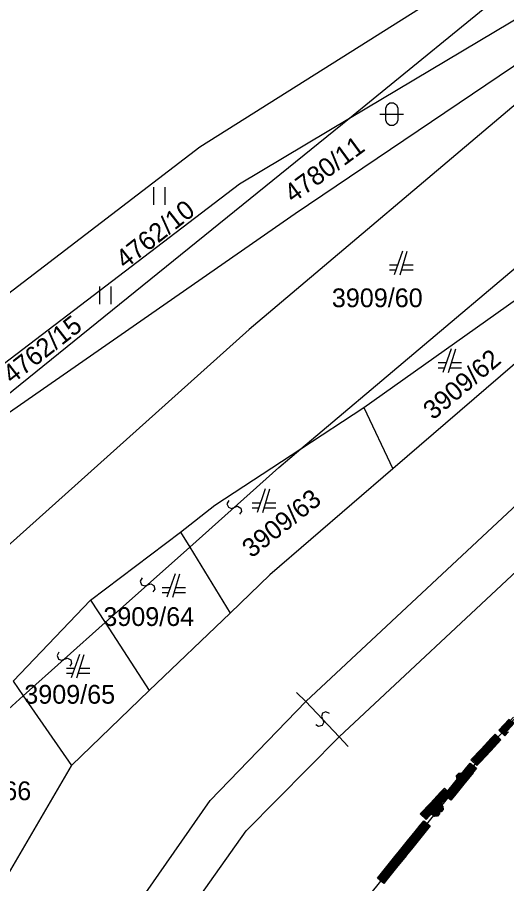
# Model space of a CAD drawing. Extents: x -266179 to -264727, y -1243225 to -1241702.
# Drawn here: x -265607.4 to -265565.7, y -1243155 to -1243081.2 of the extents above; entities that cross this region are included whole.
import ezdxf

# ---------------------------------------------------------------- set-up
doc = ezdxf.new("R2010")
doc.units = 0
for name, color, linetype in [('Vrstva 1', 7, 'Continuous'), ('Vrstva 19', 7, 'Continuous'), ('Vrstva 2', 7, 'Continuous'), ('Vrstva 21', 7, 'Continuous')]:
    doc.layers.add(name, color=color, linetype=linetype)

msp = doc.modelspace()

# ---------------------------------------------------------------- linework, layer by layer
at = {"layer": 'Vrstva 1'}
for p, q in [((-265545.67, -1243063.18), (-265591.88, -1243092.3)), ((-265579.13, -1243089.82), (-265534.79, -1243063.37)), ((-265577.11, -1243088.19), (-265556.47, -1243071.33)), ((-265563.36, -1243084.21), (-265583.76, -1243097.98)), ((-265560.69, -1243085), (-265587.67, -1243107.82)), ((-265579.13, -1243089.82), (-265577.11, -1243088.19)), ((-265622.55, -1243124.94), (-265579.13, -1243089.82)), ((-265588.51, -1243095.42), (-265579.13, -1243089.82)), ((-265591.88, -1243092.3), (-265615.8, -1243110.62)), ((-265619.14, -1243118.79), (-265588.51, -1243095.42)), ((-265595.83, -1243095.71), (-265595.83, -1243097.21)), ((-265594.83, -1243097.21), (-265594.83, -1243095.71)), ((-265583.76, -1243097.98), (-265622.55, -1243124.94)), ((-265577.91, -1243114.48), (-265559.8, -1243101.6)), ((-265574.62, -1243101.16), (-265575.32, -1243103.16)), ((-265574.82, -1243103.16), (-265574.22, -1243101.16)), ((-265575.04, -1243102.36), (-265575.72, -1243102.36)), ((-265573.72, -1243102.36), (-265574.58, -1243102.36)), ((-265575.72, -1243102.76), (-265575.18, -1243102.76)), ((-265574.7, -1243102.76), (-265573.72, -1243102.76)), ((-265600.43, -1243104.18), (-265600.43, -1243105.68)), ((-265599.43, -1243105.68), (-265599.43, -1243104.18)), ((-265558.41, -1243105), (-265575.44, -1243119.69)), ((-265587.67, -1243107.82), (-265623.99, -1243140.37)), ((-265570.49, -1243109.48), (-265571.19, -1243111.48)), ((-265570.69, -1243111.48), (-265570.09, -1243109.48)), ((-265570.91, -1243110.68), (-265571.59, -1243110.68)), ((-265569.59, -1243110.68), (-265570.45, -1243110.68)), ((-265571.59, -1243111.08), (-265571.05, -1243111.08)), ((-265570.57, -1243111.08), (-265569.59, -1243111.08)), ((-265583.27, -1243117.99), (-265577.91, -1243114.48)), ((-265577.91, -1243114.48), (-265575.44, -1243119.69)), ((-265590.59, -1243122.79), (-265583.27, -1243117.99)), ((-265575.44, -1243119.69), (-265585.91, -1243128.72)), ((-265586.31, -1243121.41), (-265587.01, -1243123.41)), ((-265586.51, -1243123.41), (-265585.91, -1243121.41)), ((-265593.52, -1243125.08), (-265590.59, -1243122.79)), ((-265586.73, -1243122.61), (-265587.41, -1243122.61)), ((-265587.41, -1243123.01), (-265586.87, -1243123.01)), ((-265586.39, -1243123.01), (-265585.41, -1243123.01)), ((-265585.41, -1243122.61), (-265586.27, -1243122.61)), ((-265601.18, -1243130.87), (-265593.52, -1243125.08)), ((-265593.52, -1243125.08), (-265592.74, -1243126.36)), ((-265592.74, -1243126.36), (-265589.31, -1243131.99)), ((-265593.99, -1243128.63), (-265594.69, -1243130.63)), ((-265594.19, -1243130.63), (-265593.59, -1243128.63)), ((-265585.91, -1243128.72), (-265589.31, -1243131.99)), ((-265594.41, -1243129.83), (-265595.09, -1243129.83)), ((-265593.09, -1243129.83), (-265593.95, -1243129.83)), ((-265595.09, -1243130.23), (-265594.55, -1243130.23)), ((-265594.07, -1243130.23), (-265593.09, -1243130.23)), ((-265607.78, -1243137.78), (-265601.18, -1243130.87)), ((-265601.18, -1243130.87), (-265599.93, -1243132.79)), ((-265589.31, -1243131.99), (-265596.18, -1243138.59)), ((-265599.93, -1243132.79), (-265596.18, -1243138.59)), ((-265602.14, -1243135.5), (-265602.84, -1243137.5)), ((-265602.34, -1243137.5), (-265601.74, -1243135.5)), ((-265602.56, -1243136.7), (-265603.24, -1243136.7)), ((-265603.24, -1243137.1), (-265602.7, -1243137.1)), ((-265602.22, -1243137.1), (-265601.24, -1243137.1)), ((-265601.24, -1243136.7), (-265602.1, -1243136.7)), ((-265607.78, -1243137.78), (-265606.91, -1243139.03)), ((-265596.18, -1243138.59), (-265602.8, -1243144.96)), ((-265606.91, -1243139.03), (-265602.8, -1243144.96)), ((-265565.22, -1243141.2), (-265567.42, -1243143.54)), ((-265567.42, -1243143.54), (-265575.88, -1243154.04)), ((-265602.84, -1243145), (-265608.61, -1243154.88)), ((-265602.8, -1243144.96), (-265602.84, -1243145)), ((-265575.88, -1243154.04), (-265581.59, -1243161.13))]:
    msp.add_line(p, q, dxfattribs=at)
msp.add_lwpolyline([(-265576.04, -1243088.99), (-265575.94, -1243088.7), (-265575.69, -1243088.52), (-265575.38, -1243088.52), (-265575.13, -1243088.7), (-265575.03, -1243088.99), (-265575.03, -1243089.99), (-265575.13, -1243090.28), (-265575.38, -1243090.46), (-265575.69, -1243090.46), (-265575.94, -1243090.28), (-265576.04, -1243089.99)], close=True, dxfattribs=at)
msp.add_lwpolyline([(-265576.54, -1243089.49), (-265575.27, -1243089.49), (-265574.54, -1243089.49)], dxfattribs=at)
at = {"layer": 'Vrstva 19'}
for p, q in [((-265565.22, -1243141.2), (-265567.42, -1243143.54)), ((-265567.42, -1243143.54), (-265575.88, -1243154.04)), ((-265575.88, -1243154.04), (-265581.59, -1243161.13))]:
    msp.add_line(p, q, dxfattribs=at)
for points in [[(-265565.161, -1243140.846), (-265566.031, -1243141.772), (-265566.264, -1243142.019), (-265566.322, -1243141.965), (-265565.452, -1243141.039)], [(-265565.044, -1243140.956), (-265565.914, -1243141.881), (-265566.147, -1243142.129), (-265566.205, -1243142.074), (-265565.336, -1243141.149)], [(-265565.582, -1243142.097), (-265565.897, -1243142.432), (-265566.407, -1243141.953), (-265565.537, -1243141.028)], [(-265564.928, -1243141.065), (-265565.798, -1243141.991), (-265566.03, -1243142.238), (-265566.089, -1243142.184), (-265565.219, -1243141.258)], [(-265565.681, -1243142.1), (-265565.914, -1243142.348), (-265565.972, -1243142.293), (-265565.102, -1243141.368)], [(-265566.233, -1243142.787), (-265567.103, -1243143.712), (-265567.972, -1243144.638), (-265568.287, -1243144.973), (-265568.797, -1243144.494), (-265567.928, -1243143.568), (-265567.058, -1243142.643), (-265566.743, -1243142.308), (-265566.233, -1243142.787), (-265566.318, -1243142.775), (-265567.188, -1243143.701), (-265568.058, -1243144.626), (-265568.29, -1243144.874), (-265568.349, -1243144.819), (-265567.479, -1243143.894), (-265566.609, -1243142.968), (-265566.376, -1243142.721), (-265566.435, -1243142.666), (-265567.304, -1243143.591), (-265568.174, -1243144.517), (-265568.407, -1243144.765), (-265568.465, -1243144.71), (-265567.596, -1243143.784), (-265566.726, -1243142.859), (-265566.493, -1243142.611), (-265566.551, -1243142.556), (-265567.421, -1243143.482), (-265568.291, -1243144.407), (-265568.524, -1243144.655), (-265568.582, -1243144.6), (-265567.712, -1243143.675), (-265566.842, -1243142.749), (-265566.61, -1243142.502), (-265566.668, -1243142.447), (-265567.538, -1243143.372), (-265568.407, -1243144.298), (-265568.64, -1243144.545), (-265568.698, -1243144.491), (-265567.829, -1243143.565), (-265566.959, -1243142.64), (-265566.726, -1243142.392)], [(-265568.611, -1243145.578), (-265569.408, -1243146.567), (-265570.205, -1243147.555), (-265570.494, -1243147.913), (-265571.039, -1243147.474), (-265570.242, -1243146.485), (-265569.445, -1243145.497), (-265569.156, -1243145.138), (-265568.611, -1243145.578), (-265568.697, -1243145.573), (-265569.494, -1243146.562), (-265570.291, -1243147.55), (-265570.504, -1243147.815), (-265570.567, -1243147.765), (-265569.77, -1243146.776), (-265568.973, -1243145.787), (-265568.759, -1243145.523), (-265568.822, -1243145.472), (-265569.619, -1243146.461), (-265570.416, -1243147.45), (-265570.629, -1243147.715), (-265570.691, -1243147.664), (-265569.894, -1243146.676), (-265569.097, -1243145.687), (-265568.884, -1243145.422), (-265568.946, -1243145.372), (-265569.743, -1243146.361), (-265570.54, -1243147.35), (-265570.754, -1243147.614), (-265570.816, -1243147.564), (-265570.019, -1243146.575), (-265569.222, -1243145.586), (-265569.009, -1243145.322), (-265569.071, -1243145.271), (-265569.868, -1243146.26), (-265570.665, -1243147.249), (-265570.878, -1243147.514), (-265570.941, -1243147.464), (-265570.144, -1243146.475), (-265569.347, -1243145.486), (-265569.133, -1243145.221)], [(-265568.308, -1243145.201), (-265569.105, -1243146.19), (-265569.902, -1243147.178), (-265570.19, -1243147.536), (-265570.735, -1243147.097), (-265569.938, -1243146.108), (-265569.141, -1243145.12), (-265568.853, -1243144.761), (-265568.308, -1243145.201), (-265568.393, -1243145.196), (-265569.19, -1243146.185), (-265569.987, -1243147.173), (-265570.201, -1243147.438), (-265570.263, -1243147.388), (-265569.466, -1243146.399), (-265568.669, -1243145.41), (-265568.456, -1243145.146), (-265568.518, -1243145.095), (-265569.315, -1243146.084), (-265570.112, -1243147.073), (-265570.325, -1243147.338), (-265570.388, -1243147.287), (-265569.591, -1243146.299), (-265568.794, -1243145.31), (-265568.58, -1243145.045), (-265568.643, -1243144.995), (-265569.44, -1243145.984), (-265570.237, -1243146.973), (-265570.45, -1243147.237), (-265570.512, -1243147.187), (-265569.715, -1243146.198), (-265568.918, -1243145.209), (-265568.705, -1243144.945), (-265568.767, -1243144.895), (-265569.564, -1243145.883), (-265570.361, -1243146.872), (-265570.574, -1243147.137), (-265570.637, -1243147.087), (-265569.84, -1243146.098), (-265569.043, -1243145.109), (-265568.829, -1243144.844)], [(-265569.35, -1243146.06), (-265569.535, -1243146.257), (-265569.804, -1243146.265), (-265570, -1243146.08), (-265570.009, -1243145.812), (-265569.824, -1243145.615), (-265569.555, -1243145.607), (-265569.358, -1243145.792), (-265569.35, -1243146.06), (-265569.386, -1243146.04), (-265569.55, -1243146.215), (-265569.664, -1243146.218), (-265569.39, -1243145.927), (-265569.393, -1243145.814), (-265569.777, -1243146.222), (-265569.835, -1243146.167), (-265569.451, -1243145.759), (-265569.51, -1243145.704), (-265569.893, -1243146.112), (-265569.952, -1243146.058), (-265569.568, -1243145.649), (-265569.681, -1243145.653), (-265569.955, -1243145.944), (-265569.959, -1243145.831), (-265569.794, -1243145.656)], [(-265570.547, -1243147.378), (-265571.417, -1243148.303), (-265572.287, -1243149.229), (-265572.602, -1243149.564), (-265573.112, -1243149.084), (-265572.242, -1243148.159), (-265571.372, -1243147.234), (-265571.057, -1243146.898), (-265570.547, -1243147.378), (-265570.646, -1243147.381), (-265571.516, -1243148.306), (-265572.386, -1243149.232), (-265572.619, -1243149.479), (-265572.677, -1243149.425), (-265571.807, -1243148.499), (-265570.937, -1243147.574), (-265570.705, -1243147.326), (-265570.763, -1243147.271), (-265571.633, -1243148.197), (-265572.502, -1243149.122), (-265572.735, -1243149.37), (-265572.793, -1243149.315), (-265571.924, -1243148.39), (-265571.054, -1243147.464), (-265570.821, -1243147.216), (-265570.879, -1243147.162), (-265571.749, -1243148.087), (-265572.619, -1243149.013), (-265572.852, -1243149.26), (-265572.91, -1243149.205), (-265572.04, -1243148.28), (-265571.171, -1243147.355), (-265570.938, -1243147.107), (-265570.996, -1243147.052), (-265571.866, -1243147.977), (-265572.736, -1243148.903), (-265572.968, -1243149.151), (-265573.027, -1243149.096), (-265572.157, -1243148.17), (-265571.287, -1243147.245), (-265571.054, -1243146.997)], [(-265571.167, -1243148.701), (-265571.337, -1243148.911), (-265571.604, -1243148.94), (-265571.814, -1243148.771), (-265571.843, -1243148.503), (-265571.673, -1243148.293), (-265571.406, -1243148.265), (-265571.196, -1243148.434), (-265571.167, -1243148.701), (-265571.205, -1243148.684), (-265571.355, -1243148.871), (-265571.468, -1243148.883), (-265571.217, -1243148.571), (-265571.229, -1243148.459), (-265571.58, -1243148.895), (-265571.643, -1243148.845), (-265571.291, -1243148.409), (-265571.354, -1243148.358), (-265571.705, -1243148.794), (-265571.767, -1243148.744), (-265571.416, -1243148.308), (-265571.528, -1243148.32), (-265571.779, -1243148.632), (-265571.791, -1243148.519), (-265571.641, -1243148.332)], [(-265571.471, -1243149.078), (-265571.641, -1243149.288), (-265571.908, -1243149.317), (-265572.118, -1243149.148), (-265572.147, -1243148.88), (-265571.977, -1243148.67), (-265571.71, -1243148.641), (-265571.5, -1243148.811), (-265571.471, -1243149.078), (-265571.509, -1243149.061), (-265571.659, -1243149.248), (-265571.772, -1243149.26), (-265571.521, -1243148.948), (-265571.533, -1243148.836), (-265571.884, -1243149.272), (-265571.946, -1243149.222), (-265571.595, -1243148.786), (-265571.657, -1243148.735), (-265572.009, -1243149.171), (-265572.071, -1243149.121), (-265571.72, -1243148.685), (-265571.832, -1243148.697), (-265572.083, -1243149.009), (-265572.095, -1243148.896), (-265571.945, -1243148.709)], [(-265572.261, -1243150.106), (-265573.058, -1243151.095), (-265573.855, -1243152.083), (-265574.144, -1243152.442), (-265574.689, -1243152.002), (-265573.892, -1243151.013), (-265573.095, -1243150.025), (-265572.806, -1243149.667), (-265572.261, -1243150.106), (-265572.359, -1243150.116), (-265573.156, -1243151.105), (-265573.953, -1243152.094), (-265574.167, -1243152.359), (-265574.229, -1243152.309), (-265573.432, -1243151.32), (-265572.635, -1243150.331), (-265572.422, -1243150.066), (-265572.484, -1243150.016), (-265573.281, -1243151.005), (-265574.078, -1243151.994), (-265574.291, -1243152.258), (-265574.354, -1243152.208), (-265573.557, -1243151.219), (-265572.76, -1243150.23), (-265572.546, -1243149.966), (-265572.609, -1243149.916), (-265573.406, -1243150.904), (-265574.203, -1243151.893), (-265574.416, -1243152.158), (-265574.478, -1243152.108), (-265573.681, -1243151.119), (-265572.884, -1243150.13), (-265572.671, -1243149.865), (-265572.733, -1243149.815), (-265573.53, -1243150.804), (-265574.327, -1243151.793), (-265574.541, -1243152.057), (-265574.603, -1243152.007), (-265573.806, -1243151.018), (-265573.009, -1243150.03), (-265572.796, -1243149.765)], [(-265572.565, -1243150.483), (-265573.362, -1243151.472), (-265574.159, -1243152.46), (-265574.447, -1243152.819), (-265574.992, -1243152.379), (-265574.195, -1243151.39), (-265573.398, -1243150.402), (-265573.11, -1243150.044), (-265572.565, -1243150.483), (-265572.663, -1243150.493), (-265573.46, -1243151.482), (-265574.257, -1243152.471), (-265574.471, -1243152.736), (-265574.533, -1243152.685), (-265573.736, -1243151.697), (-265572.939, -1243150.708), (-265572.726, -1243150.443), (-265572.788, -1243150.393), (-265573.585, -1243151.382), (-265574.382, -1243152.371), (-265574.595, -1243152.635), (-265574.657, -1243152.585), (-265573.86, -1243151.596), (-265573.063, -1243150.607), (-265572.85, -1243150.343), (-265572.912, -1243150.293), (-265573.709, -1243151.281), (-265574.506, -1243152.27), (-265574.72, -1243152.535), (-265574.782, -1243152.485), (-265573.985, -1243151.496), (-265573.188, -1243150.507), (-265572.975, -1243150.242), (-265573.037, -1243150.192), (-265573.834, -1243151.181), (-265574.631, -1243152.17), (-265574.844, -1243152.434), (-265574.907, -1243152.384), (-265574.11, -1243151.395), (-265573.313, -1243150.407), (-265573.099, -1243150.142)], [(-265574.322, -1243152.667), (-265575.119, -1243153.656), (-265575.916, -1243154.644), (-265576.205, -1243155.003), (-265576.75, -1243154.563), (-265575.953, -1243153.575), (-265575.156, -1243152.586), (-265574.867, -1243152.228), (-265574.322, -1243152.667), (-265574.408, -1243152.662), (-265575.205, -1243153.651), (-265576.002, -1243154.639), (-265576.216, -1243154.904), (-265576.278, -1243154.854), (-265575.481, -1243153.865), (-265574.684, -1243152.876), (-265574.471, -1243152.612), (-265574.533, -1243152.561), (-265575.33, -1243153.55), (-265576.127, -1243154.539), (-265576.34, -1243154.804), (-265576.402, -1243154.754), (-265575.605, -1243153.765), (-265574.808, -1243152.776), (-265574.595, -1243152.511), (-265574.657, -1243152.461), (-265575.454, -1243153.45), (-265576.251, -1243154.439), (-265576.465, -1243154.703), (-265576.527, -1243154.653), (-265575.73, -1243153.664), (-265574.933, -1243152.676), (-265574.72, -1243152.411), (-265574.782, -1243152.361), (-265575.579, -1243153.349), (-265576.376, -1243154.338), (-265576.589, -1243154.603), (-265576.652, -1243154.553), (-265575.855, -1243153.564), (-265575.058, -1243152.575), (-265574.844, -1243152.31)]]:
    msp.add_lwpolyline(points, dxfattribs=at)
at = {"layer": 'Vrstva 2'}
for p, q in [((-265583.27, -1243117.99), (-265558.79, -1243097.3)), ((-265585.16, -1243119.59), (-265583.27, -1243117.99)), ((-265592.74, -1243126.36), (-265585.16, -1243119.59)), ((-265582.84, -1243139.51), (-265564.83, -1243122.67)), ((-265580.02, -1243142.51), (-265561.87, -1243125.56)), ((-265599.93, -1243132.79), (-265592.74, -1243126.36)), ((-265606.91, -1243139.03), (-265599.93, -1243132.79)), ((-265583.64, -1243138.75), (-265582.84, -1243139.51)), ((-265615.04, -1243146.29), (-265606.91, -1243139.03)), ((-265591, -1243147.94), (-265582.84, -1243139.51)), ((-265582.84, -1243139.51), (-265580.02, -1243142.51)), ((-265587.92, -1243150.53), (-265580.02, -1243142.51)), ((-265580.02, -1243142.51), (-265579.24, -1243143.34)), ((-265598.5, -1243158.68), (-265591, -1243147.94)), ((-265595.02, -1243160.53), (-265587.92, -1243150.53))]:
    msp.add_line(p, q, dxfattribs=at)
for points in [[(-265589.412, -1243122.382), (-265589.57, -1243122.671), (-265589.452, -1243122.968), (-265589.181, -1243123.061), (-265588.675, -1243122.877), (-265588.401, -1243123.034), (-265588.34, -1243123.342), (-265588.488, -1243123.568)], [(-265596.798, -1243128.983), (-265596.956, -1243129.271), (-265596.837, -1243129.568), (-265596.566, -1243129.661), (-265596.06, -1243129.477), (-265595.786, -1243129.634), (-265595.725, -1243129.942), (-265595.872, -1243130.167)], [(-265603.882, -1243135.317), (-265604.04, -1243135.606), (-265603.922, -1243135.903), (-265603.651, -1243135.996), (-265603.145, -1243135.812), (-265602.871, -1243135.969), (-265602.81, -1243136.277), (-265602.958, -1243136.503)], [(-265580.849, -1243140.533), (-265581.142, -1243140.382), (-265581.436, -1243140.508), (-265581.522, -1243140.781), (-265581.325, -1243141.282), (-265581.475, -1243141.56), (-265581.782, -1243141.629), (-265582.011, -1243141.487)]]:
    msp.add_lwpolyline(points, dxfattribs=at)
at = {"layer": 'Vrstva 21'}
for p, q in [((-265565.22, -1243141.2), (-265567.42, -1243143.54)), ((-265567.42, -1243143.54), (-265575.88, -1243154.04)), ((-265575.88, -1243154.04), (-265581.59, -1243161.13))]:
    msp.add_line(p, q, dxfattribs=at)

# ---------------------------------------------------------------- texts
at = {"layer": 'Vrstva 1'}
for s, rotation, p in [('4780/11', 36.21093, (-265583.94, -1243097.106)), ('4762/10', 38.21629, (-265598.239, -1243102.725)), ('4762/15', 37.9871, (-265607.87, -1243112.523)), ('3909/62', 40.22164, (-265572.012, -1243115.593)), ('3909/63', 38.33088, (-265587.476, -1243127.349))]:
    msp.add_text(s, height=1.6, rotation=rotation, dxfattribs=at).set_placement(p)
for s, p in [('3909/60', (-265580.636, -1243105.93)), ('3909/64', (-265600.097, -1243133.08)), ('3909/65', (-265606.827, -1243139.7)), ('3909/66', (-265613.971, -1243147.92))]:
    msp.add_text(s, height=1.6, dxfattribs=at).set_placement(p)

doc.saveas('drawing.dxf')
